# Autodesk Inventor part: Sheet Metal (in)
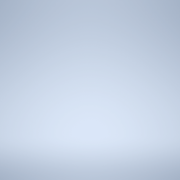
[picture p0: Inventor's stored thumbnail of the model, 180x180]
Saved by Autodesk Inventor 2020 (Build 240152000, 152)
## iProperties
Created: 2019-02
Part Number: Sheet Metal (in)
Material: Ogólny
Document SubType Name: Konstrukcja blachowa
Density: 1 g/cm^3
Sheet Metal Rule: Domyślny
Appearance: Domyślna
Designer: F.Stasiak
Manager: www.cadconsulting.pl
Company: Fabian Stasiak CAD Consulting
Subject: Zbiór ćwiczeń. Autodesk Inventor 2020. Kurs podstawowy
Author: F.Stasiak
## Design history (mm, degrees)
other parameters: "Grubość" = 3.048, "WspółczynnikK" = 4.4, "PromieńGięcia" = 3.048 (= Grubość), "SzerokośćGięciaPodcięcia" = 3.048 (= Grubość), "GłębokośćGięciaPodcięcia" = 1.524 (= 0.5 x Grubość), "RozmiarPodcięciaNarożnika" = 12.192 (= 4 x Grubość), "OdstępPołączenia" = 0.00508, "MinimalnaPozostałość" = 6.096 (= 2 x Grubość), "PromieńPrzejścia" = 3.048 (= PromieńGięcia), "Rozmiar_promienia_Jacobiego" = 3.048 (= Grubość), "Wielk_odstępu" = 3.048 (= Grubość)
